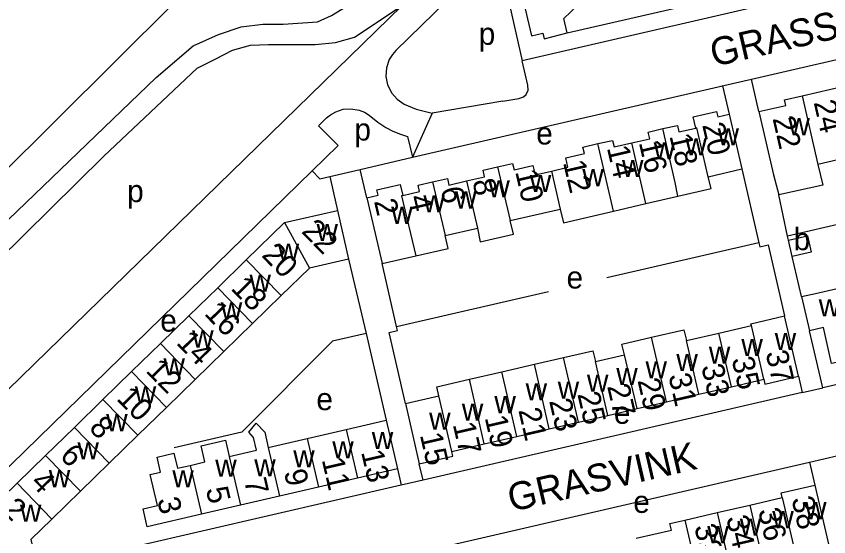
# Model space of a CAD drawing. Extents: x 155696 to 157795, y 382328 to 384028.
# Drawn here: x 156567.7 to 156713.8, y 383421.4 to 383515 of the extents above; entities that cross this region are included whole.
import ezdxf

# ---------------------------------------------------------------- set-up
doc = ezdxf.new("R2010")
doc.units = 0
for name, color, linetype in [('BLT_Basislijn', 7, 'Continuous'), ('BLT_Bebouwing', 7, 'Continuous'), ('BLT_Centroide', 7, 'Continuous'), ('BLT_Huisnummer', 7, 'Continuous'), ('BLT_Huisnummer_ tussenligend', 7, 'Continuous'), ('BLT_Huisnummer_reeks', 7, 'Continuous'), ('BLT_Onderverdeling_panden', 7, 'Continuous'), ('BLT_Straatnaam', 7, 'Continuous'), ('BLT_Vlakafsluiter', 7, 'Continuous')]:
    doc.layers.add(name, color=color, linetype=linetype)

msp = doc.modelspace()

# ---------------------------------------------------------------- linework, layer by layer
at = {"layer": 'BLT_Basislijn'}
for p, q in [((156655.48, 383520.95), (156658.68, 383507.04)), ((156539.06, 383460.86), (156596.07, 383517.45)), ((156666.76, 383512.04), (156689.3, 383517.19)), ((156600.21, 383505.72), (156583.42, 383489.84)), ((156694.4, 383502.46), (156699.88, 383503.73)), ((156655.18, 383499.78), (156642.47, 383497.6)), ((156540.18, 383447.24), (156583.42, 383489.84)), ((156620.9, 383487.22), (156560.36, 383428.2)), ((156624.07, 383486.22), (156629.52, 383487.48)), ((156706.4, 383475.47), (156704.84, 383482.89)), ((156727.45, 383480.34), (156706.4, 383475.47)), ((156701.22, 383474.28), (156673.9, 383467.97)), ((156636.05, 383459.22), (156663.37, 383465.53)), ((156709.03, 383447.34), (156712.71, 383448.19)), ((156710.34, 383434.82), (156715.52, 383436.01)), ((156640.84, 383431.59), (156636.9, 383430.68))]:
    msp.add_line(p, q, dxfattribs=at)
for points in [[(156539.63, 383452.94), (156592.84, 383504.01), (156599.46, 383509.72), (156604.03, 383511.77), (156608.14, 383513.14), (156612.02, 383513.6), (156615.67, 383513.6), (156621.84, 383514.06), (156624.35, 383515.2), (156627.78, 383517.26), (156630.97, 383520), (156635.77, 383523.65), (156704.27, 383589.66), (156708.15, 383591.95), (156712.49, 383594.69), (156790.55, 383624.17)], [(156768.88, 383532.5), (156658.68, 383507.04)], [(156652.15, 383524.7), (156635.94, 383508.89), (156635.34, 383508.18), (156634.75, 383507.25), (156634.26, 383505.76), (156634.16, 383504.23), (156634.45, 383502.73), (156635.2, 383501.19), (156636.17, 383500.12), (156637.44, 383499.24), (156639.61, 383498.3), (156642.47, 383497.6)], [(156699.88, 383503.73), (156771.7, 383520.32)], [(156637.05, 383516.96), (156566.16, 383447.85), (156556.85, 383438.91)], [(156600.21, 383505.72), (156603.58, 383507.4), (156606.56, 383508.96), (156609.81, 383509.81), (156613.06, 383509.95), (156617.31, 383509.95), (156621.41, 383509.95), (156625.07, 383510.3), (156628.49, 383511.28), (156637.05, 383516.96)], [(156655.18, 383499.78), (156658.04, 383500.22), (156658.91, 383500.55), (156659.38, 383500.99), (156659.73, 383501.72), (156659.7, 383502.66), (156658.68, 383507.04)], [(156638.96, 383489.66), (156694.69, 383502.53), (156695.89, 383497.41)], [(156701.23, 383497.88), (156699.88, 383503.73)], [(156620.9, 383487.22), (156625.54, 383491.77), (156622.05, 383495.35), (156623.48, 383496.75), (156624.19, 383497.33), (156625.16, 383497.87), (156626.45, 383498.3), (156627.82, 383498.4), (156629.33, 383498.17), (156630.3, 383497.79), (156631.15, 383497.24), (156632.71, 383495.98), (156634.14, 383495.04), (156635.39, 383494.39), (156636.77, 383493.82), (156638.02, 383493.43), (156638.96, 383489.66)], [(156629.52, 383487.48), (156638.96, 383489.66)], [(156622.28, 383485.81), (156620.9, 383487.22)], [(156630.7, 383482.38), (156629.52, 383487.48)], [(156698.15, 383487.56), (156701.22, 383474.28)], [(156622.28, 383485.81), (156624.07, 383486.22)], [(156624.07, 383486.22), (156624.75, 383483.3)], [(156624.75, 383483.3), (156625.42, 383480.11)], [(156706.57, 383474.74), (156706.4, 383475.47)], [(156701.22, 383474.28), (156701.39, 383473.55), (156702.9, 383473.89), (156705.85, 383461.12)], [(156708.91, 383464.61), (156707.23, 383471.82)], [(156627.45, 383471.34), (156630.6, 383457.96)], [(156636.05, 383459.22), (156633.45, 383470.54)], [(156784.52, 383464.78), (156712.71, 383448.19), (156710.34, 383458.45)], [(156637.66, 383445.37), (156634.71, 383458.14), (156636.22, 383458.49), (156636.05, 383459.22)], [(156630.6, 383457.96), (156624.56, 383456.57), (156608.22, 383440.22), (156596.04, 383437.41)], [(156630.6, 383457.96), (156634.2, 383442.37)], [(156708.36, 383450.27), (156709.03, 383447.34), (156640.84, 383431.59), (156640.16, 383434.52)], [(156645.16, 383419.76), (156710.34, 383434.82), (156711.29, 383430.7)], [(156636.23, 383433.61), (156636.9, 383430.68), (156565.3, 383414.14)]]:
    msp.add_lwpolyline(points, dxfattribs=at)
at = {"layer": 'BLT_Bebouwing'}
for p, q in [((156658.44, 383519.66), (156660.32, 383511.5)), ((156708.99, 383500.7), (156716.78, 383502.5)), ((156695.89, 383497.41), (156698.15, 383487.56)), ((156719.63, 383490.18), (156711.84, 383488.38)), ((156692.12, 383486.16), (156698.15, 383487.56)), ((156630.7, 383482.38), (156633.45, 383470.54)), ((156680.92, 383481.33), (156686.67, 383482.66)), ((156615.9, 383477.91), (156625.42, 383480.11)), ((156625.42, 383480.11), (156627.45, 383471.34)), ((156656.48, 383478.27), (156665.49, 383480.35)), ((156609.04, 383471.23), (156615.9, 383477.91)), ((156644.79, 383475.57), (156650.63, 383476.92)), ((156707.23, 383471.82), (156706.57, 383474.74)), ((156633.45, 383470.54), (156639.52, 383471.94)), ((156603.89, 383466.2), (156609.04, 383471.23)), ((156627.45, 383471.34), (156620.38, 383469.71)), ((156620.38, 383469.71), (156615.32, 383464.78)), ((156598.73, 383461.17), (156603.89, 383466.2)), ((156615.32, 383464.78), (156610.17, 383459.76)), ((156708.91, 383464.61), (156710.34, 383458.45)), ((156593.58, 383456.15), (156598.73, 383461.17)), ((156708.36, 383450.27), (156705.85, 383461.12)), ((156610.17, 383459.76), (156605.01, 383454.73)), ((156694.04, 383458.05), (156699.89, 383459.41)), ((156688.2, 383456.7), (156694.04, 383458.05)), ((156588.42, 383451.12), (156593.58, 383456.15)), ((156605.01, 383454.73), (156599.86, 383449.7)), ((156671.83, 383452.92), (156677.09, 383454.14)), ((156660.86, 383452.43), (156666.09, 383453.64)), ((156583.26, 383446.1), (156588.42, 383451.12)), ((156599.86, 383449.7), (156594.7, 383444.68)), ((156649.18, 383449.73), (156655.01, 383451.08)), ((156696.28, 383448.37), (156702.12, 383449.72)), ((156690.43, 383447.02), (156696.28, 383448.37)), ((156684.59, 383445.67), (156690.43, 383447.02)), ((156578.11, 383441.07), (156583.26, 383446.1)), ((156637.66, 383445.37), (156643.69, 383446.76)), ((156637.66, 383445.37), (156640.16, 383434.52)), ((156679.33, 383444.45), (156684.59, 383445.67)), ((156594.7, 383444.68), (156589.55, 383439.65)), ((156674.06, 383443.24), (156679.33, 383444.45)), ((156668.8, 383442.02), (156674.06, 383443.24)), ((156572.95, 383436.04), (156578.11, 383441.07)), ((156627, 383440.71), (156634.2, 383442.37)), ((156634.2, 383442.37), (156636.23, 383433.61)), ((156663.54, 383440.81), (156668.8, 383442.02)), ((156589.55, 383439.65), (156584.39, 383434.62)), ((156619.98, 383439.09), (156627, 383440.71)), ((156657.7, 383439.46), (156663.54, 383440.81)), ((156612.96, 383437.47), (156619.98, 383439.09)), ((156651.85, 383438.11), (156657.7, 383439.46)), ((156567.8, 383431.02), (156572.95, 383436.04)), ((156584.39, 383434.62), (156579.24, 383429.6)), ((156636.23, 383433.61), (156629.02, 383431.94)), ((156629.02, 383431.94), (156622.01, 383430.32)), ((156579.24, 383429.6), (156574.08, 383424.57)), ((156622.01, 383430.32), (156614.99, 383428.7)), ((156711.29, 383430.7), (156713.8, 383419.84)), ((156614.99, 383428.7), (156607.98, 383427.08)), ((156699.6, 383427.1), (156705.45, 383428.45)), ((156607.98, 383427.08), (156600.96, 383425.46)), ((156693.76, 383425.75), (156699.6, 383427.1)), ((156600.96, 383425.46), (156591.22, 383423.21)), ((156687.91, 383424.4), (156693.76, 383425.75))]:
    msp.add_line(p, q, dxfattribs=at)
for points in [[(156666.76, 383512.04), (156666.16, 383514.62), (156669.95, 383518.3)], [(156660.32, 383511.5), (156662.38, 383511.97), (156662.61, 383510.99), (156666.76, 383512.04)], [(156701.23, 383497.88), (156706.1, 383499.01), (156705.87, 383499.98), (156708.99, 383500.7)], [(156689.89, 383494.93), (156689.43, 383496.95), (156693.61, 383497.91), (156693.83, 383496.93), (156695.89, 383497.41)], [(156701.23, 383497.88), (156703.87, 383486.52), (156704.84, 383482.89)], [(156683.96, 383494.82), (156686.6, 383495.39), (156686.86, 383494.22), (156689.89, 383494.93)], [(156678.39, 383492.27), (156681.61, 383493.01), (156681.34, 383494.18), (156683.96, 383494.82)], [(156663.91, 383487.18), (156666.89, 383487.86), (156666.51, 383489.54), (156669.86, 383490.33), (156669.59, 383491.5), (156672.27, 383492.12)], [(156672.27, 383492.12), (156674.91, 383492.7), (156675.18, 383491.54), (156678.39, 383492.27)], [(156648.67, 383485.41), (156651.91, 383486.17), (156651.64, 383487.34), (156654.24, 383487.95)], [(156654.24, 383487.95), (156656.92, 383488.57), (156657.19, 383487.4), (156660.59, 383488.18), (156660.97, 383486.51), (156663.91, 383487.18)], [(156711.84, 383488.38), (156712.75, 383484.65), (156704.84, 383482.89)], [(156630.7, 383482.38), (156632.76, 383482.87), (156632.65, 383483.35), (156632.54, 383483.84), (156636.72, 383484.79), (156637.18, 383482.77)], [(156637.18, 383482.77), (156640.18, 383483.5), (156639.93, 383484.67), (156642.55, 383485.25)], [(156642.55, 383485.25), (156645.23, 383485.83), (156645.49, 383484.66), (156648.67, 383485.41)], [(156686.67, 383482.66), (156692.63, 383484.03), (156692.12, 383486.16)], [(156675.07, 383479.98), (156680.92, 383481.33)], [(156665.49, 383480.35), (156666.08, 383477.9), (156675.07, 383479.98)], [(156650.63, 383476.92), (156651.13, 383474.44), (156657.07, 383475.81), (156656.48, 383478.27)], [(156639.52, 383471.94), (156645.34, 383473.27), (156644.79, 383475.57)], [(156706.57, 383474.74), (156709.97, 383475.51), (156710.63, 383472.59), (156707.23, 383471.82)], [(156708.91, 383464.61), (156711.41, 383465.18), (156716.85, 383466.4), (156717.52, 383463.48)], [(156699.89, 383459.41), (156699.81, 383459.73), (156705.85, 383461.12)], [(156681.89, 383457.29), (156687.73, 383458.64), (156688.2, 383456.7)], [(156719.76, 383453.79), (156714.32, 383452.54), (156712.83, 383459.02), (156710.34, 383458.45)], [(156677.09, 383454.14), (156676.61, 383456.07), (156681.89, 383457.29)], [(156666.09, 383453.64), (156671.35, 383454.85), (156671.83, 383452.92)], [(156655.01, 383451.08), (156660.87, 383452.43), (156660.87, 383452.43)], [(156643.69, 383446.76), (156643.33, 383448.38), (156649.18, 383449.73)], [(156702.12, 383449.72), (156702.32, 383448.87), (156708.36, 383450.27)], [(156605.95, 383435.85), (156610.85, 383436.98), (156610.33, 383439.25), (156609.51, 383440.23), (156610.83, 383441.81), (156612.37, 383440.19), (156612.96, 383437.47)], [(156598.93, 383434.23), (156601.61, 383434.85), (156600.94, 383437.77), (156605.28, 383438.77), (156605.95, 383435.85)], [(156646, 383436.76), (156651.85, 383438.11)], [(156640.16, 383434.52), (156646.2, 383435.91), (156646, 383436.76)], [(156591.77, 383432.57), (156593.62, 383433.01), (156592.99, 383435.7), (156596.03, 383436.42), (156596.67, 383433.73), (156598.93, 383434.23)], [(156591.22, 383423.21), (156590.5, 383426.43), (156593.05, 383427.01), (156591.77, 383432.57)], [(156562.58, 383425.92), (156567.8, 383431.02)], [(156705.45, 383428.45), (156705.25, 383429.3), (156711.29, 383430.7)], [(156574.08, 383424.57), (156570.3, 383420.88), (156570.89, 383418.31), (156566.8, 383417.37), (156566.58, 383418.34), (156564.44, 383417.85)], [(156679.17, 383421.15), (156685.5, 383422.61), (156685.23, 383423.78), (156687.91, 383424.4)]]:
    msp.add_lwpolyline(points, dxfattribs=at)
at = {"layer": 'BLT_Onderverdeling_panden'}
for p, q in [((156708.99, 383500.7), (156711.84, 383488.38)), ((156675.07, 383479.98), (156672.27, 383492.12)), ((156680.92, 383481.33), (156678.39, 383492.27)), ((156654.24, 383487.95), (156656.48, 383478.27)), ((156663.91, 383487.18), (156665.49, 383480.35)), ((156642.55, 383485.25), (156644.79, 383475.57)), ((156648.67, 383485.41), (156650.63, 383476.92)), ((156615.9, 383477.91), (156620.38, 383469.71)), ((156609.04, 383471.23), (156615.32, 383464.78)), ((156603.89, 383466.2), (156610.17, 383459.76)), ((156598.73, 383461.17), (156605.01, 383454.73)), ((156702.12, 383449.72), (156699.89, 383459.41)), ((156684.59, 383445.67), (156681.89, 383457.29)), ((156696.28, 383448.37), (156694.04, 383458.05)), ((156593.58, 383456.15), (156599.86, 383449.7)), ((156690.43, 383447.02), (156688.2, 383456.7)), ((156679.33, 383444.45), (156677.09, 383454.14)), ((156668.8, 383442.02), (156666.09, 383453.64)), ((156674.06, 383443.24), (156671.83, 383452.92)), ((156663.54, 383440.81), (156660.86, 383452.43)), ((156588.42, 383451.12), (156594.7, 383444.68)), ((156651.85, 383438.11), (156649.18, 383449.73)), ((156657.7, 383439.46), (156655.01, 383451.08)), ((156583.26, 383446.1), (156589.55, 383439.65)), ((156646, 383436.76), (156643.69, 383446.76)), ((156578.11, 383441.07), (156584.39, 383434.62)), ((156627, 383440.71), (156629.02, 383431.94)), ((156619.98, 383439.09), (156622.01, 383430.32)), ((156612.96, 383437.47), (156614.99, 383428.7)), ((156572.95, 383436.04), (156579.24, 383429.6)), ((156605.95, 383435.85), (156607.98, 383427.08)), ((156598.93, 383434.23), (156600.96, 383425.46)), ((156567.8, 383431.02), (156574.08, 383424.57)), ((156705.45, 383428.45), (156707.68, 383418.77)), ((156699.6, 383427.1), (156701.84, 383417.42)), ((156693.76, 383425.75), (156695.99, 383416.07)), ((156687.91, 383424.4), (156690.15, 383414.72))]:
    msp.add_line(p, q, dxfattribs=at)
for points in [[(156686.67, 383482.66), (156686.2, 383485.13), (156683.96, 383494.82)], [(156692.12, 383486.16), (156690.08, 383494.98), (156689.89, 383494.93)], [(156637.18, 383482.77), (156636.98, 383482.72), (156639.52, 383471.94)]]:
    msp.add_lwpolyline(points, dxfattribs=at)
at = {"layer": 'BLT_Vlakafsluiter'}
msp.add_line((156642.47, 383497.6), (156638.96, 383489.66), dxfattribs=at)

# ---------------------------------------------------------------- texts
at = {"layer": 'BLT_Centroide'}
for s, p in [('p', (156650.85, 383509.9)), ('w', (156706.53, 383493.64)), ('p', (156628.49, 383492.68)), ('e', (156661.19, 383491.97)), ('w', (156693.8, 383491.83)), ('w', (156682.3, 383489.31)), ('w', (156688, 383490.03)), ('w', (156676.61, 383486.11)), ('w', (156660.03, 383483.41)), ('w', (156669.48, 383484.47)), ('w', (156652.58, 383482.47)), ('p', (156587.61, 383481.6)), ('w', (156646.59, 383480.45)), ('w', (156640.88, 383479.77)), ('w', (156635.11, 383477.69)), ('w', (156621.67, 383474.62)), ('b', (156707.49, 383472.95)), ('w', (156614.7, 383471.08)), ('e', (156666.64, 383466.05)), ('w', (156609.61, 383465.5)), ('w', (156604.45, 383460.47)), ('w', (156711.99, 383461.06)), ('e', (156593.57, 383458.3)), ('w', (156599.3, 383455.44)), ('w', (156704.08, 383455)), ('w', (156692.23, 383452.53)), ('w', (156698.08, 383453.89)), ('w', (156686.39, 383451.19)), ('w', (156594.14, 383450.41)), ('w', (156680.84, 383449.91)), ('w', (156675.58, 383448.69)), ('w', (156670.31, 383447.47)), ('w', (156588.98, 383445.38)), ('w', (156659.28, 383445.94)), ('w', (156665.05, 383446.25)), ('e', (156621.64, 383444.17)), ('w', (156647.81, 383442.28)), ('w', (156653.66, 383443.62)), ('e', (156675.15, 383441.72)), ('w', (156583.83, 383440.38)), ('w', (156641.92, 383440.64)), ('w', (156631.61, 383437.16)), ('w', (156578.67, 383435.34)), ('w', (156624.5, 383435.52)), ('w', (156617.48, 383433.89)), ('w', (156603.45, 383432.19)), ('w', (156610.47, 383432.28)), ('w', (156573.52, 383430.31)), ('w', (156595.73, 383430.3)), ('e', (156678.64, 383425.69)), ('w', (156568.33, 383424.09)), ('w', (156709.53, 383424.56)), ('w', (156703.64, 383422.94)), ('w', (156697.8, 383421.59)), ('w', (156691.95, 383420.23))]:
    msp.add_text(s, height=4, dxfattribs=at).set_placement(p)
at = {"layer": 'BLT_Huisnummer'}
for s, rotation, p in [('22', 283.0058, (156703.67, 383496.66)), ('20', 283.0058, (156691.02, 383495.49)), ('16', 283.0058, (156679.62, 383492.34)), ('12', 283.0058, (156666, 383488.74)), ('10', 283.0058, (156657.39, 383487.08)), ('6', 283.0058, (156643.94, 383483.95)), ('2', 283.0058, (156631.99, 383481.78)), ('22', 314.2752, (156618.82, 383476.22)), ('18', 314.2752, (156606.11, 383465.97)), ('14', 314.2752, (156596.3, 383456.17)), ('37', 283.0086, (156702.41, 383454.51)), ('33', 283.0086, (156690.85, 383452.05)), ('29', 283.0086, (156679.38, 383449.52)), ('27', 283.0086, (156673.92, 383448.49)), ('10', 314.2752, (156585.55, 383446.12)), ('23', 283.0086, (156663.49, 383445.84)), ('19', 283.0086, (156651.9, 383442.84)), ('15', 283.0086, (156640.24, 383439.73)), ('6', 314.2752, (156575.32, 383435.78)), ('13', 283.0086, (156629.67, 383436.64)), ('11', 283.0086, (156622.59, 383435.27)), ('7', 283.0086, (156608.61, 383431.54)), ('3', 283.0086, (156592.99, 383428.09)), ('38', 283.0041, (156707.08, 383428.22)), ('34', 283.0041, (156695.33, 383424.83))]:
    msp.add_text(s, height=4, rotation=rotation, dxfattribs=at).set_placement(p)
at = {"layer": 'BLT_Huisnummer_ tussenligend'}
for s, rotation, p in [('24', 283.0058, (156711.07, 383499.55)), ('18', 283.0058, (156685.12, 383493.53)), ('14', 283.0058, (156673.88, 383491.38)), ('8', 283.0058, (156649.68, 383485.38)), ('4', 283.0058, (156638.2, 383482.51)), ('20', 314.2752, (156611.64, 383471.92)), ('16', 314.2752, (156601.32, 383461.43)), ('12', 314.2752, (156590.82, 383451.14)), ('35', 283.0086, (156696.3, 383453.37)), ('31', 283.0086, (156684.93, 383450.39)), ('25', 283.0086, (156668.57, 383447.07)), ('21', 283.0086, (156657.95, 383444.18)), ('8', 314.2752, (156580.58, 383440.8)), ('17', 283.0086, (156646.16, 383441.62)), ('4', 314.2752, (156570.06, 383430.99)), ('9', 283.0086, (156615.79, 383433.1)), ('5', 283.0086, (156601.74, 383429.97)), ('36', 283.0041, (156701.07, 383426.14)), ('32', 283.0041, (156689.59, 383423.25))]:
    msp.add_text(s, height=4, rotation=rotation, dxfattribs=at).set_placement(p)
at = {"layer": 'BLT_Huisnummer_reeks'}
msp.add_text('2', height=4, rotation=314.2752, dxfattribs=at).set_placement((156564.92, 383426.08))
at = {"layer": 'BLT_Straatnaam'}
for s, rotation, p in [('GRASSNIP', 13.0063, (156693.12, 383505.93)), ('GRASVINK', 13.0062, (156656.71, 383425.86))]:
    msp.add_text(s, height=5, rotation=rotation, dxfattribs=at).set_placement(p)

doc.saveas('drawing.dxf')
